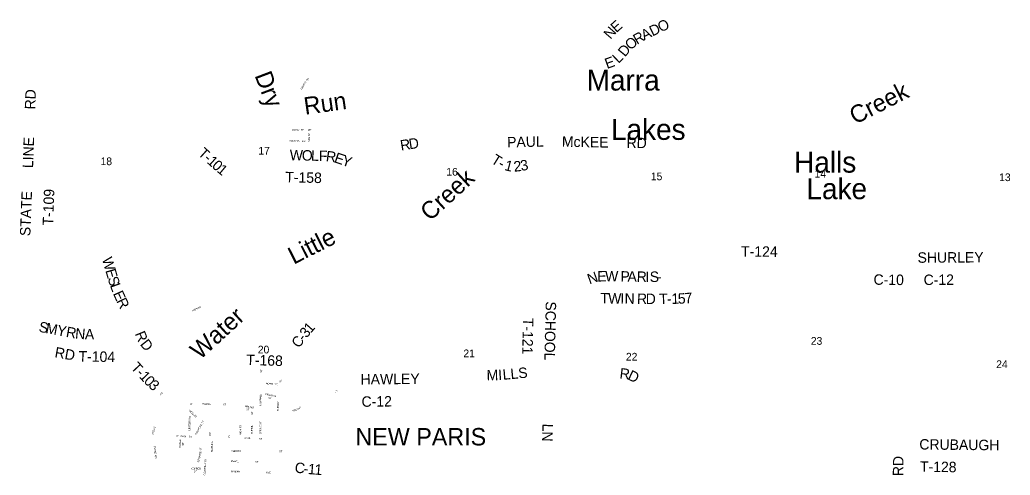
# Model space of a CAD drawing. Extents: x -21.9 to 47.3, y 14.1 to 48.7.
# Drawn here: x 2.192 to 6.25, y 19.03 to 20.899 of the extents above; entities that cross this region are included whole.
import ezdxf

# ---------------------------------------------------------------- set-up
doc = ezdxf.new("R2010")
doc.units = 0
for name, color, linetype in [('GM_X_City_Street_Text', 7, 'Continuous'), ('GM_X_Corporation_Text', 7, 'Continuous'), ('GM_X_County_Road_Text', 7, 'Continuous'), ('GM_X_Minor_Lake_Text', 7, 'Continuous'), ('GM_X_Minor_River_Text', 7, 'Continuous'), ('GM_X_Section_Text', 7, 'Continuous'), ('GM_X_Township_Road_Text', 7, 'Continuous'), ('GM_X_Township_Subdivision_Text', 7, 'Continuous')]:
    doc.layers.add(name, color=color, linetype=linetype)

msp = doc.modelspace()

# ---------------------------------------------------------------- texts
at = {"layer": 'GM_X_City_Street_Text'}
for s, height, rotation, p in [('ST', 0.00714, 86.4237, (3.1844, 19.4514)), ('NORTH ST', 0.00714, 355.7938, (3.1996, 19.403)), ('ST', 0.00714, 32.7312, (3.2573, 19.4097)), ('SPRING', 0.00714, 87.663, (3.1812, 19.3244)), ('CENTRAL', 0.00714, 349.2181, (3.1966, 19.3596)), ('ST', 0.00714, 21.7901, (3.4844, 19.3696)), ('W', 0.00714, 0, (2.8896, 19.32)), ('WALNUT', 0.00714, 358.3643, (2.9393, 19.3194)), ('ST', 0.00714, 356.4256, (3.0236, 19.3169)), ('N', 0.00714, 90, (3.1812, 19.3149)), ('ST', 0.00714, 348.682, (3.2093, 19.3444)), ('BURLEY', 0.00714, 88.9765, (3.2529, 19.2942)), ('WESLER', 0.00714, 315.7269, (2.8837, 19.2945)), ('W', 0.00714, 348.7129, (3.1143, 19.3105)), ('ST', 0.00714, 352.8654, (3.119, 19.2971)), ('A', 0.00714, 348.7155, (3.1223, 19.3089)), ('L', 0.00714, 348.6988, (3.1285, 19.3077)), ('N', 0.00714, 348.7196, (3.1334, 19.3067)), ('ST', 0.00714, 90, (3.1479, 19.2791)), ('U', 0.00714, 348.7147, (3.1396, 19.3055)), ('T', 0.00714, 348.7202, (3.1458, 19.3043)), ('W', 0.00714, 21.6445, (3.3103, 19.2904)), ('A', 0.00714, 21.6452, (3.3179, 19.2934)), ('L', 0.00714, 21.6302, (3.3237, 19.2957)), ('N', 0.00714, 23.9555, (3.3287, 19.2977)), ('U', 0.00714, 32.1617, (3.3354, 19.3008)), ('T', 0.00714, 33.0341, (3.3408, 19.3042)), ('O', 0.00714, 89.937, (2.8902, 19.2338)), ('N', 0.00714, 89.9317, (2.8902, 19.2451)), ('L', 0.00714, 89.9317, (2.8902, 19.2401)), ('A', 0.00714, 88.5739, (2.8902, 19.2532)), ('V', 0.00714, 77.3407, (2.8903, 19.2592)), ('E', 0.00714, 68.0385, (2.8916, 19.265)), ('RAILROAD ST', 0.007143, 59.2486, (2.9149, 19.1955)), ('C', 0.00714, 89.9302, (2.8902, 19.2281)), ('N', 0.00714, 89.9317, (2.8902, 19.2219)), ('I', 0.00714, 89.9317, (2.8902, 19.2187)), ('L', 0.00714, 89.9317, (2.8902, 19.2137)), ('RD', 0.00714, 273.013, (2.9664, 19.2056)), ('HIGH ST', 0.00714, 88.9392, (3.0995, 19.1955)), ('T', 0.00714, 88.9175, (3.1466, 19.2174)), ('T', 0.00714, 89.9761, (3.1466, 19.2124)), ('U', 0.00714, 89.9781, (3.1466, 19.2061)), ('H', 0.00714, 89.9781, (3.1466, 19.1999)), ('O', 0.00714, 87.8688, (3.1467, 19.2224)), ('N', 0.00714, 87.7978, (3.147, 19.2287)), ('W', 0.00714, 0, (2.8324, 19.188)), ('WATER', 0.00714, 87.6628, (2.8512, 19.1415)), ('MAIN', 0.00714, 356.3451, (2.8482, 19.1874)), ('ST', 0.00714, 90, (2.8641, 19.1521)), ('ST', 0.00714, 356.4256, (2.8841, 19.1849)), ('MAPLE ST', 0.00714, 89.1448, (2.9826, 19.1263)), ('E', 0.00714, 0, (3.0468, 19.1849)), ('MAIN', 0.00714, 356.9076, (3.1129, 19.1798)), ('ST', 0.00714, 356.4257, (3.1713, 19.1761)), ('FREED RD', 0.00714, 275.9647, (2.7407, 19.1491)), ('S', 0.00714, 82.0957, (2.9343, 19.1117)), ('O', 0.00714, 87.6869, (2.935, 19.1174)), ('N', 0.00714, 87.7108, (2.9353, 19.1237)), ('S', 0.00714, 87.709, (2.9356, 19.1319)), ('T', 0.00714, 87.709, (2.9358, 19.1369)), ('CHERRY', 0.00714, 0, (3.0575, 19.1251)), ('ST', 0.00714, 0, (3.2548, 19.1245)), ('J', 0.00714, 79.0876, (2.926, 19.0826)), ('E', 0.00714, 79.0866, (2.9266, 19.0856)), ('F', 0.00714, 77.0338, (2.9276, 19.0905)), ('F', 0.00714, 73.5748, (2.9287, 19.0953)), ('E', 0.00714, 68.9259, (2.93, 19.1)), ('R', 0.00714, 69.5314, (2.9319, 19.1047)), ('COBLENTZ ST', 0.007143, 86.8892, (2.9524, 19.0296)), ('PEARL', 0.00714, 357.3989, (3.0563, 19.0849)), ('ST', 0.00714, 356.412, (3.1562, 19.0818)), ('KEMPER', 0.00714, 0, (2.8922, 19.0535)), ('ST', 0.00714, 0, (2.9054, 19.0412)), ('WRENN', 0.00714, 357.7512, (3.0563, 19.0428)), ('AVE', 0.00714, 358.0186, (3.2002, 19.0378))]:
    msp.add_text(s, height=height, rotation=rotation, dxfattribs=at).set_placement(p)
at = {"layer": 'GM_X_Corporation_Text'}
msp.add_text('NEW PARIS', height=0.07143, rotation=0, dxfattribs=at).set_placement((3.5671, 19.1524))
at = {"layer": 'GM_X_County_Road_Text'}
for s, height, rotation, p in [('N', 0.0429, 49.1036, (4.6126, 20.8164)), ('E', 0.0429, 41.5588, (4.6363, 20.8439)), ('A', 0.0429, 26.6382, (4.7507, 20.8134)), ('D', 0.0429, 25.5513, (4.7842, 20.8302)), ('O', 0.0429, 26.0258, (4.8186, 20.8467)), ('O', 0.0429, 41.7285, (4.6947, 20.7721)), ('R', 0.0429, 30.5103, (4.7211, 20.7959)), ('D', 0.0429, 50.8423, (4.6721, 20.7442)), ('E', 0.0429, 19.7966, (4.5982, 20.6968)), ('L', 0.0429, 43.338, (4.6446, 20.7177)), ('SHURLEY', 0.04286, 0.2986, (5.8709, 19.9019)), ('C-10', 0.04286, 359.3142, (5.6903, 19.8118)), ('C-12', 0.04286, 0.3429, (5.8959, 19.8105)), ('1', 0.0429, 48.4214, (3.3836, 19.6108)), ('3', 0.0429, 50.9877, (3.3673, 19.5907)), ('C', 0.0429, 51.8877, (3.3348, 19.5493)), ('-', 0.0429, 51.6929, (3.3565, 19.577)), ('HAWLEY', 0.04286, 0.6351, (3.5884, 19.4021)), ('M', 0.0429, 1.3883, (4.1052, 19.4191)), ('I', 0.0429, 3.4928, (4.1534, 19.4203)), ('L', 0.0429, 5.0278, (4.1723, 19.4215)), ('L', 0.0429, 5.3956, (4.2045, 19.4243)), ('S', 0.0429, 5.4008, (4.2364, 19.4273)), ('R', 0.0429, 353.3304, (4.6482, 19.4278)), ('D', 0.0429, 334.828, (4.6797, 19.4247)), ('C-12', 0.04286, 0.6871, (3.5926, 19.3108)), ('C', 0.0429, 352.1303, (3.3164, 19.042)), ('1', 0.0429, 355.2071, (3.3713, 19.0352)), ('RD', 0.04286, 89.0123, (5.812, 19.026)), ('-', 0.0429, 354.338, (3.3531, 19.037)), ('1', 0.0429, 355.5351, (3.3979, 19.033))]:
    msp.add_text(s, height=height, rotation=rotation, dxfattribs=at).set_placement(p)
at = {"layer": 'GM_X_Minor_Lake_Text'}
for s, rotation, p in [('Marra', 0.009, (4.5148, 20.6085)), ('Lakes', 0.0087, (4.6143, 20.4061)), ('Halls', 0.0068, (5.365, 20.2718)), ('Lake', 0.0066, (5.4154, 20.1628))]:
    msp.add_text(s, height=0.08571, rotation=rotation, dxfattribs=at).set_placement(p)
at = {"layer": 'GM_X_Minor_River_Text'}
for s, height, rotation, p in [('Dry', 0.07139, 290.8709, (3.1532, 20.671)), ('Creek', 0.07142, 26.8717, (5.6147, 20.4679)), ('Run', 0.07142, 8.066, (3.361, 20.5089)), ('Creek', 0.07141, 42.358, (3.8729, 20.07)), ('Little', 0.07142, 26.8728, (3.3141, 19.8936)), ('Water', 0.0714, 42.3535, (2.9302, 19.5013))]:
    msp.add_text(s, height=height, rotation=rotation, dxfattribs=at).set_placement(p)
at = {"layer": 'GM_X_Section_Text'}
for s, p in [('17', (3.1694, 20.3456)), ('18', (2.5229, 20.3024)), ('16', (3.9397, 20.2594)), ('15', (4.7779, 20.2406)), ('14', (5.4489, 20.2511)), ('13', (6.2053, 20.237)), ('23', (5.4335, 19.5654)), ('20', (3.1672, 19.5299)), ('21', (4.0097, 19.5144)), ('22', (4.6757, 19.5006)), ('24', (6.1931, 19.4698))]:
    msp.add_text(s, height=0.03157, rotation=0, dxfattribs=at).set_placement(p)
at = {"layer": 'GM_X_Township_Road_Text'}
for s, height, rotation, p in [('RD', 0.04286, 88.025, (2.2549, 20.5305)), ('PAUL', 0.04286, 1.324, (4.1893, 20.3752)), ('McKEE', 0.04286, 358.7853, (4.413, 20.3783)), ('RD', 0.04286, 359.0201, (4.678, 20.3733)), ('LINE', 0.04286, 87.9954, (2.2461, 20.2897)), ('T', 0.0429, 318.2633, (2.9191, 20.3464)), ('R', 0.0429, 9.176, (3.7544, 20.3617)), ('D', 0.0429, 8.206, (3.7889, 20.3673)), ('-', 0.0429, 318.2807, (2.943, 20.3251)), ('1', 0.0429, 318.3405, (2.9562, 20.3133)), ('W', 0.0429, 358.4809, (3.2974, 20.323)), ('O', 0.0429, 358.4808, (3.347, 20.3217)), ('L', 0.0429, 358.4842, (3.3847, 20.3207)), ('F', 0.0429, 358.3843, (3.4168, 20.3198)), ('R', 0.0429, 352.5005, (3.4445, 20.3191)), ('E', 0.0429, 341.1707, (3.4772, 20.315)), ('Y', 0.0429, 340.9914, (3.5075, 20.3047)), ('T', 0.0429, 328.1145, (4.1199, 20.3141)), ('0', 0.0429, 318.5942, (2.976, 20.2956)), ('1', 0.0429, 320.1977, (2.9968, 20.2773)), ('-', 0.0429, 330.3448, (4.1486, 20.2963)), ('1', 0.0429, 345.412, (4.1753, 20.2829)), ('2', 0.0429, 6.3204, (4.2178, 20.2751)), ('3', 0.0429, 10.0835, (4.247, 20.2784)), ('T-158', 0.04286, 358.5957, (3.2794, 20.2324)), ('STATE', 0.04286, 87.7889, (2.2348, 20.0107)), ('T-109', 0.04286, 87.7543, (2.3279, 20.0543)), ('T-124', 0.04286, 359.7182, (5.1477, 19.9269)), ('W', 0.0429, 286.1453, (2.528, 19.918)), ('E', 0.0429, 286.2818, (2.5419, 19.8702)), ('N', 0.0429, 19.3325, (4.5264, 19.8128)), ('E', 0.0429, 1.7917, (4.5586, 19.8246)), ('W', 0.0429, 359.3139, (4.5901, 19.8256)), ('P', 0.0429, 359.0439, (4.6529, 19.8248)), ('A', 0.0429, 359.0456, (4.6818, 19.8243)), ('R', 0.0429, 359.0932, (4.7196, 19.8237)), ('I', 0.0429, 359.5901, (4.7552, 19.8231)), ('S', 0.0429, 0.4098, (4.7735, 19.823)), ('S', 0.0429, 287.5511, (2.5512, 19.8385)), ('L', 0.0429, 289.94, (2.5605, 19.809)), ('-', 0.0429, 1.189, (4.803, 19.8232)), ('E', 0.0429, 294.2139, (2.5728, 19.7757)), ('T', 0.0429, 359.1428, (4.5706, 19.7353)), ('W', 0.0429, 359.1423, (4.6026, 19.7348)), ('I', 0.0429, 359.1487, (4.6523, 19.7341)), ('N', 0.0429, 359.1488, (4.6699, 19.7338)), ('R', 0.0429, 359.2883, (4.7209, 19.733)), ('D', 0.0429, 0.0146, (4.7567, 19.7326)), ('T', 0.0429, 1.0843, (4.8126, 19.7321)), ('1', 0.0429, 1.2713, (4.8624, 19.733)), ('5', 0.0429, 1.7976, (4.8892, 19.7336)), ('7', 0.0429, 5.1816, (4.9183, 19.7346)), ('R', 0.0429, 295.9774, (2.5865, 19.7451)), ('SCHOOL', 0.04286, 268.6237, (4.3472, 19.7438)), ('-', 0.0429, 1.1269, (4.8447, 19.7327)), ('S', 0.0429, 349.3478, (2.2672, 19.6192)), ('M', 0.0429, 349.3492, (2.2956, 19.6139)), ('Y', 0.0429, 349.3493, (2.3413, 19.6053)), ('T-121', 0.04286, 268.5959, (4.2541, 19.6762)), ('R', 0.0429, 349.9506, (2.3789, 19.5982)), ('N', 0.0429, 354.6135, (2.4173, 19.5916)), ('A', 0.0429, 358.7331, (2.4582, 19.5879)), ('R', 0.0429, 292.2853, (2.6627, 19.6108)), ('D', 0.0429, 308.6394, (2.6827, 19.5669)), ('RD', 0.04286, 350.0492, (2.3326, 19.5145)), ('T-104', 0.04286, 358.881, (2.4323, 19.497)), ('T-168', 0.04286, 358.3069, (3.1194, 19.4825)), ('T', 0.0429, 313.0373, (2.6442, 19.4697)), ('-', 0.0429, 313.1288, (2.6662, 19.4462)), ('1', 0.0429, 313.4822, (2.6784, 19.4331)), ('0', 0.0429, 314.8559, (2.6973, 19.4132)), ('3', 0.0429, 319.2632, (2.7166, 19.3938)), ('LN', 0.04286, 268.4517, (4.334, 19.2421)), ('CRUBAUGH', 0.04286, 359.3882, (5.878, 19.1357)), ('T-128', 0.04286, 359.1579, (5.8805, 19.0444))]:
    msp.add_text(s, height=height, rotation=rotation, dxfattribs=at).set_placement(p)
at = {"layer": 'GM_X_Township_Subdivision_Text'}
for s, rotation, p in [('D', 21.4351, (3.3723, 20.6505)), ('ARNETT', 58.3248, (3.3467, 20.6104)), ('R', 48.7661, (3.3693, 20.6468)), ('DOROTHY', 0, (3.3076, 20.4439)), ('GAIL DR', 86.9332, (3.3798, 20.3961)), ('DR', 0, (3.3724, 20.4439)), ('SANDRA', 358.9955, (3.2963, 20.3986)), ('DR', 0, (3.3479, 20.3974)), ('H&W', 24.3044, (2.9004, 19.7021)), ('RD', 25.1996, (2.923, 19.7121)), ('R', 53.6875, (2.7704, 19.357)), ('D', 48.1344, (2.7736, 19.3615)), ('SPRING ST', 90, (3.1818, 19.198)), ('FREED', 76.6075, (2.7401, 19.197))]:
    msp.add_text(s, height=0.00714, rotation=rotation, dxfattribs=at).set_placement(p)

doc.saveas('drawing.dxf')
